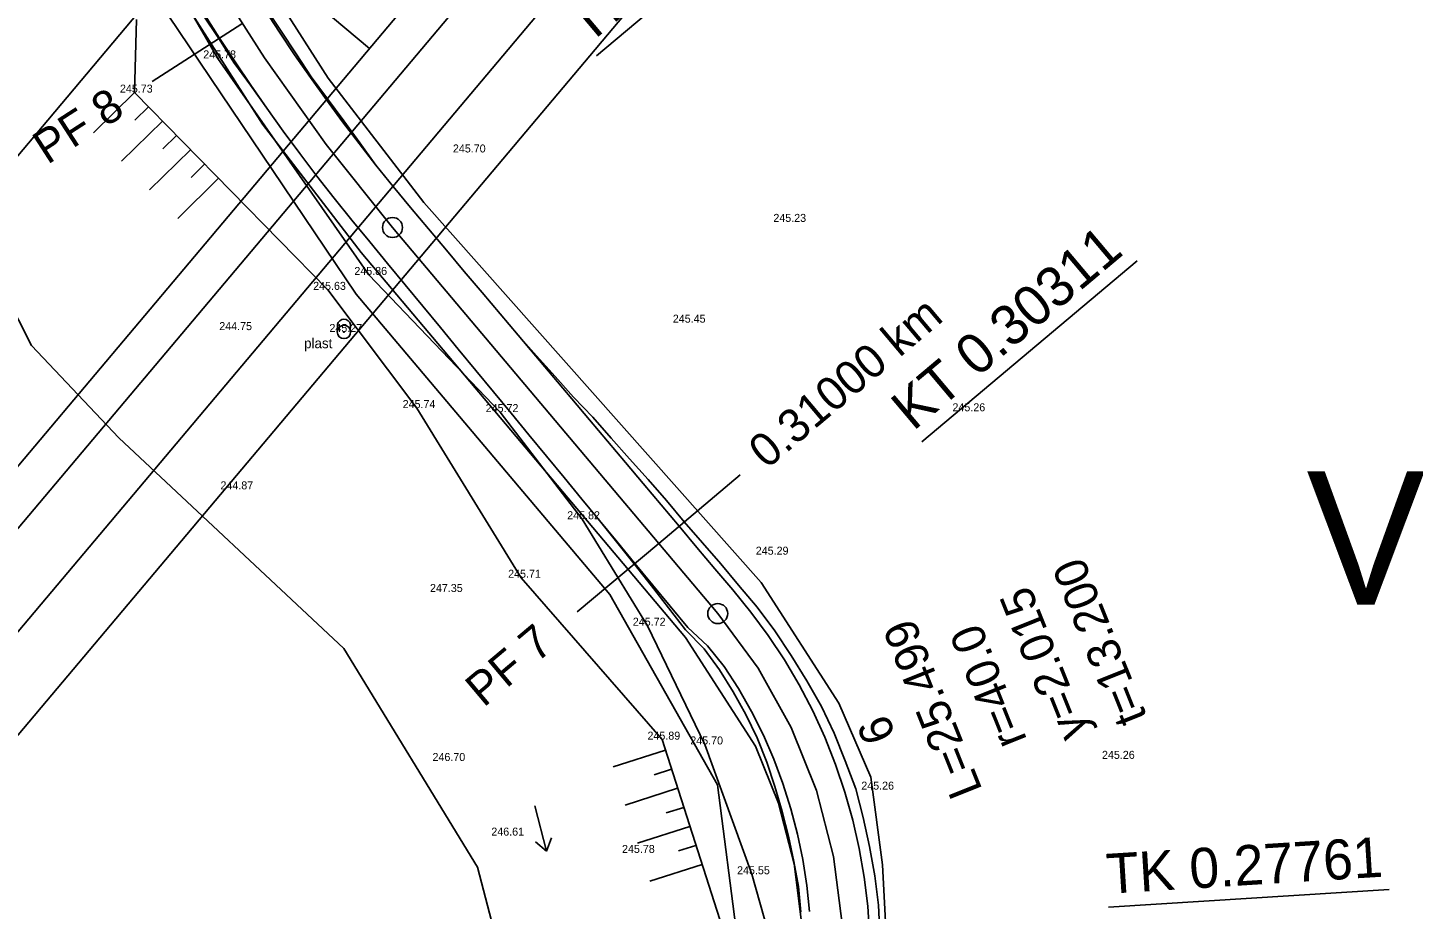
# Model space of a CAD drawing. Extents: x -555887 to -552101, y -1100251 to -1096546.
# Drawn here: x -554197.5 to -554093.6, y -1097070.3 to -1097004.2 of the extents above; entities that cross this region are included whole.
import ezdxf

# ---------------------------------------------------------------- set-up
doc = ezdxf.new("R2010")
doc.units = 0
for name, color, linetype in [('PARCELY_cesty', 7, 'Continuous'), ('PARCELY_VHO', 7, 'Continuous'), ('POLYGONY_POPIS_CESTY', 7, 'Continuous'), ('POLYGONY_SITUACE_PF', 7, 'Continuous'), ('POLYGONY_SITUACE_PF_POPISY', 7, 'Continuous'), ('POLYGONY_SITUACE_PO', 7, 'Continuous'), ('ram_VC2', 7, 'Continuous'), ('Výškopis', 7, 'Continuous'), ('ZSST', 7, 'Continuous'), ('zájem', 7, 'Continuous')]:
    doc.layers.add(name, color=color, linetype=linetype)

msp = doc.modelspace()

# ---------------------------------------------------------------- linework, layer by layer
for p, q in [((-554154.8, -1097006.31), (-554138.67, -1096992.72)), ((-554130.41, -1097035.28), (-554114.27, -1097021.69)), ((-554116.42, -1097070.19), (-554095.37, -1097068.87))]:
    msp.add_line(p, q)
at = {"layer": 'PARCELY_cesty'}
for points in [[(-554115.45, -1097149.45), (-554124.69, -1097127.01), (-554128.78, -1097114.84), (-554130.72, -1097105.51), (-554131.84, -1097095.95), (-554133.35, -1097067.01), (-554134.24, -1097060.44), (-554136.63, -1097054.87), (-554142.45, -1097045.83), (-554167.76, -1097017.31), (-554174.93, -1097007.99), (-554183.34, -1096994.77), (-554188.76, -1096984.33), (-554196.7, -1096967.2), (-554199.93, -1096958.08), (-554201.74, -1096948.89), (-554201.83, -1096939.45), (-554200.52, -1096930.03), (-554198.73, -1096923.96), (-554169.26, -1096840.86), (-554169, -1096840.13)], [(-554120.97, -1097151.79), (-554130.31, -1097129.11), (-554134.59, -1097116.42), (-554136.65, -1097106.48), (-554137.82, -1097096.49), (-554139.37, -1097071.71), (-554139.97, -1097066.94), (-554141.16, -1097062.38), (-554142.87, -1097058.1), (-554148.12, -1097049.95), (-554172.44, -1097021.07), (-554179.85, -1097011.43), (-554188.55, -1096997.77)]]:
    msp.add_lwpolyline(points, dxfattribs=at)
at = {"layer": 'PARCELY_VHO'}
for points in [[(-554130.46, -1097180.06), (-554159.17, -1097101.34), (-554159.64, -1097082.93), (-554163.72, -1097067.19), (-554173.74, -1097050.79), (-554190.63, -1097034.96), (-554197.16, -1097028.05), (-554217.46, -1096987.98), (-554225.33, -1096977.64), (-554234.21, -1096944.26), (-554236.99, -1096909.92), (-554235.22, -1096898.62), (-554228.6, -1096882.13), (-554225.73, -1096869.26), (-554224.9, -1096864.61), (-554220.11, -1096846.63), (-554200.4, -1096831.93), (-554179.17, -1096807.62), (-554142.08, -1096773.53), (-554110.69, -1096747.36), (-554089.18, -1096729.49)], [(-554093.55, -1096750.72), (-554107.61, -1096766.97), (-554183.58, -1096830.32), (-554190.17, -1096868.02), (-554206.15, -1096921.51), (-554210.92, -1096940.13), (-554208.99, -1096958.65), (-554201.43, -1096978.3), (-554189.25, -1096999.78), (-554172.82, -1097024.19), (-554153.8, -1097046.73), (-554145.73, -1097061.02), (-554142.77, -1097083.92), (-554141.5, -1097107.04), (-554133.09, -1097133.96)]]:
    msp.add_lwpolyline(points, dxfattribs=at)
at = {"layer": 'POLYGONY_SITUACE_PF'}
for p, q in [((-554188.12, -1097008.24), (-554181.39, -1097003.91)), ((-554150.14, -1097042.89), (-554144.02, -1097037.74)), ((-554156.26, -1097048.04), (-554150.14, -1097042.89))]:
    msp.add_line(p, q, dxfattribs=at)
at = {"layer": 'POLYGONY_SITUACE_PO'}
for p, q in [((-554179.71, -1097006.47), (-554183.99, -1096999.74)), ((-554178.58, -1097004.54), (-554179.71, -1097002.82)), ((-554178.58, -1097004.54), (-554179.71, -1097002.82)), ((-554178.45, -1097004.45), (-554179.59, -1097002.74)), ((-554183.12, -1097005.02), (-554184.29, -1097003.26)), ((-554183.08, -1097004.99), (-554184.2, -1097003.21)), ((-554181.99, -1097006.81), (-554183.12, -1097005.02)), ((-554181.91, -1097006.75), (-554183.08, -1097004.99)), ((-554177.44, -1097006.24), (-554178.58, -1097004.54)), ((-554177.44, -1097006.24), (-554178.58, -1097004.54)), ((-554177.33, -1097006.17), (-554178.45, -1097004.45)), ((-554180.74, -1097008.51), (-554181.99, -1097006.81)), ((-554180.73, -1097008.5), (-554181.91, -1097006.75)), ((-554175.07, -1097012.96), (-554179.71, -1097006.47)), ((-554176.26, -1097007.93), (-554177.44, -1097006.24)), ((-554176.26, -1097007.93), (-554177.44, -1097006.24)), ((-554176.2, -1097007.89), (-554177.33, -1097006.17)), ((-554175.06, -1097009.6), (-554176.26, -1097007.93)), ((-554175.06, -1097009.6), (-554176.26, -1097007.93)), ((-554174.97, -1097009.53), (-554176.2, -1097007.89)), ((-554179.53, -1097010.24), (-554180.74, -1097008.51)), ((-554179.53, -1097010.24), (-554180.73, -1097008.5)), ((-554178.3, -1097011.95), (-554179.53, -1097010.24)), ((-554179.53, -1097010.24), (-554179.53, -1097010.24)), ((-554178.3, -1097011.95), (-554179.53, -1097010.24)), ((-554173.85, -1097011.26), (-554175.06, -1097009.6)), ((-554173.85, -1097011.26), (-554175.06, -1097009.6)), ((-554173.76, -1097011.19), (-554174.97, -1097009.53)), ((-554172.6, -1097012.89), (-554173.85, -1097011.26)), ((-554172.6, -1097012.89), (-554173.85, -1097011.26)), ((-554172.54, -1097012.85), (-554173.76, -1097011.19)), ((-554177.05, -1097013.65), (-554178.3, -1097011.95)), ((-554177.05, -1097013.65), (-554178.3, -1097011.95)), ((-554170.1, -1097019.19), (-554175.07, -1097012.96)), ((-554171.34, -1097014.51), (-554172.6, -1097012.89)), ((-554171.34, -1097014.51), (-554172.6, -1097012.89)), ((-554171.34, -1097014.51), (-554172.54, -1097012.85)), ((-554175.77, -1097015.33), (-554177.05, -1097013.65)), ((-554175.77, -1097015.33), (-554177.05, -1097013.65)), ((-554174.47, -1097017), (-554175.77, -1097015.33)), ((-554174.47, -1097017), (-554175.77, -1097015.33)), ((-554170.05, -1097016.12), (-554171.34, -1097014.51)), ((-554170.05, -1097016.12), (-554171.34, -1097014.51)), ((-554170.05, -1097016.12), (-554171.34, -1097014.51)), ((-554171.34, -1097014.51), (-554171.34, -1097014.51)), ((-554168.74, -1097017.7), (-554170.05, -1097016.12)), ((-554168.74, -1097017.7), (-554170.05, -1097016.12)), ((-554168.74, -1097017.7), (-554170.05, -1097016.12)), ((-554173.15, -1097018.64), (-554174.47, -1097017)), ((-554173.15, -1097018.64), (-554174.47, -1097017)), ((-554167.4, -1097019.29), (-554168.74, -1097017.7)), ((-554167.4, -1097019.29), (-554168.74, -1097017.7)), ((-554167.4, -1097019.29), (-554168.74, -1097017.7)), ((-554171.8, -1097020.27), (-554173.15, -1097018.64)), ((-554171.8, -1097020.27), (-554173.15, -1097018.64)), ((-554145.71, -1097048.16), (-554170.1, -1097019.19)), ((-554166.06, -1097020.88), (-554167.4, -1097019.29)), ((-554166.06, -1097020.88), (-554167.4, -1097019.29)), ((-554166.06, -1097020.88), (-554167.4, -1097019.29)), ((-554170.47, -1097021.88), (-554171.8, -1097020.27)), ((-554170.47, -1097021.88), (-554171.8, -1097020.27)), ((-554164.72, -1097022.48), (-554166.06, -1097020.88)), ((-554164.72, -1097022.48), (-554166.06, -1097020.88)), ((-554164.72, -1097022.48), (-554166.06, -1097020.88)), ((-554169.15, -1097023.49), (-554170.47, -1097021.88)), ((-554169.15, -1097023.49), (-554170.47, -1097021.88)), ((-554163.37, -1097024.07), (-554164.72, -1097022.48)), ((-554163.37, -1097024.07), (-554164.72, -1097022.48)), ((-554163.37, -1097024.07), (-554164.72, -1097022.48)), ((-554167.82, -1097025.1), (-554169.15, -1097023.49)), ((-554167.82, -1097025.1), (-554169.15, -1097023.49)), ((-554162.03, -1097025.67), (-554163.37, -1097024.07)), ((-554162.03, -1097025.67), (-554163.37, -1097024.07)), ((-554162.03, -1097025.67), (-554163.37, -1097024.07)), ((-554166.5, -1097026.7), (-554167.82, -1097025.1)), ((-554166.5, -1097026.7), (-554167.82, -1097025.1)), ((-554160.69, -1097027.26), (-554162.03, -1097025.67)), ((-554160.69, -1097027.26), (-554162.03, -1097025.67)), ((-554160.69, -1097027.26), (-554162.03, -1097025.67)), ((-554165.17, -1097028.31), (-554166.5, -1097026.7)), ((-554165.17, -1097028.31), (-554166.5, -1097026.7)), ((-554159.35, -1097028.85), (-554160.69, -1097027.26)), ((-554159.35, -1097028.85), (-554160.69, -1097027.26)), ((-554159.3, -1097028.81), (-554160.69, -1097027.26)), ((-554160.69, -1097027.26), (-554160.69, -1097027.26)), ((-554163.85, -1097029.92), (-554165.17, -1097028.31)), ((-554163.85, -1097029.92), (-554165.17, -1097028.31)), ((-554158.01, -1097030.45), (-554159.35, -1097028.85)), ((-554158.01, -1097030.45), (-554159.35, -1097028.85)), ((-554157.91, -1097030.37), (-554159.3, -1097028.81)), ((-554162.52, -1097031.53), (-554163.85, -1097029.92)), ((-554162.52, -1097031.53), (-554163.85, -1097029.92)), ((-554156.66, -1097032.04), (-554158.01, -1097030.45)), ((-554156.66, -1097032.04), (-554158.01, -1097030.45)), ((-554156.53, -1097031.92), (-554157.91, -1097030.37)), ((-554161.2, -1097033.13), (-554162.52, -1097031.53)), ((-554161.2, -1097033.13), (-554162.52, -1097031.53)), ((-554155.32, -1097033.63), (-554156.66, -1097032.04)), ((-554155.32, -1097033.63), (-554156.66, -1097032.04)), ((-554155.07, -1097033.42), (-554156.53, -1097031.92)), ((-554159.87, -1097034.74), (-554161.2, -1097033.13)), ((-554159.87, -1097034.74), (-554161.2, -1097033.13)), ((-554153.98, -1097035.23), (-554155.32, -1097033.63)), ((-554153.98, -1097035.23), (-554155.32, -1097033.63)), ((-554153.71, -1097035), (-554155.07, -1097033.42)), ((-554158.55, -1097036.35), (-554159.87, -1097034.74)), ((-554158.55, -1097036.35), (-554159.87, -1097034.74)), ((-554152.64, -1097036.82), (-554153.98, -1097035.23)), ((-554152.64, -1097036.82), (-554153.98, -1097035.23)), ((-554152.33, -1097036.56), (-554153.71, -1097035)), ((-554157.22, -1097037.96), (-554158.55, -1097036.35)), ((-554157.22, -1097037.96), (-554158.55, -1097036.35)), ((-554151.3, -1097038.41), (-554152.64, -1097036.82)), ((-554151.3, -1097038.41), (-554152.64, -1097036.82)), ((-554150.93, -1097038.1), (-554152.33, -1097036.56)), ((-554155.9, -1097039.57), (-554157.22, -1097037.96)), ((-554155.9, -1097039.57), (-554157.22, -1097037.96)), ((-554149.56, -1097039.68), (-554150.93, -1097038.1)), ((-554149.96, -1097040.01), (-554151.3, -1097038.41)), ((-554149.96, -1097040.01), (-554151.3, -1097038.41)), ((-554154.57, -1097041.17), (-554155.9, -1097039.57)), ((-554154.57, -1097041.17), (-554155.9, -1097039.57)), ((-554148.61, -1097041.6), (-554149.96, -1097040.01)), ((-554148.61, -1097041.6), (-554149.96, -1097040.01)), ((-554148.22, -1097041.27), (-554149.56, -1097039.68)), ((-554153.27, -1097042.8), (-554154.57, -1097041.17)), ((-554154.57, -1097041.17), (-554154.57, -1097041.17)), ((-554153.25, -1097042.78), (-554154.57, -1097041.17)), ((-554146.85, -1097042.84), (-554148.22, -1097041.27)), ((-554147.27, -1097043.2), (-554148.61, -1097041.6)), ((-554147.27, -1097043.2), (-554148.61, -1097041.6)), ((-554151.97, -1097044.43), (-554153.27, -1097042.8)), ((-554151.92, -1097044.39), (-554153.25, -1097042.78)), ((-554145.93, -1097044.79), (-554147.27, -1097043.2)), ((-554145.93, -1097044.79), (-554147.27, -1097043.2)), ((-554145.49, -1097044.42), (-554146.85, -1097042.84)), ((-554150.68, -1097046.07), (-554151.97, -1097044.43)), ((-554150.6, -1097046), (-554151.92, -1097044.39)), ((-554144.15, -1097046.02), (-554145.49, -1097044.42)), ((-554144.59, -1097046.38), (-554145.93, -1097044.79)), ((-554144.59, -1097046.38), (-554145.93, -1097044.79)), ((-554149.41, -1097047.72), (-554150.68, -1097046.07)), ((-554149.27, -1097047.6), (-554150.6, -1097046)), ((-554143.22, -1097048.05), (-554144.59, -1097046.38)), ((-554143.22, -1097048.05), (-554144.59, -1097046.38)), ((-554142.75, -1097047.68), (-554144.15, -1097046.02)), ((-554147.95, -1097049.21), (-554149.27, -1097047.6)), ((-554141.43, -1097049.46), (-554142.75, -1097047.68)), ((-554148.14, -1097049.37), (-554149.41, -1097047.72)), ((-554142.68, -1097052.26), (-554145.71, -1097048.16)), ((-554141.92, -1097049.81), (-554143.22, -1097048.05)), ((-554141.92, -1097049.81), (-554143.22, -1097048.05)), ((-554146.74, -1097050.8), (-554148.14, -1097049.37)), ((-554146.47, -1097050.59), (-554147.95, -1097049.21)), ((-554140.21, -1097051.31), (-554141.43, -1097049.46)), ((-554145.57, -1097052.37), (-554146.74, -1097050.8)), ((-554145.22, -1097052.12), (-554146.47, -1097050.59)), ((-554140.71, -1097051.63), (-554141.92, -1097049.81)), ((-554140.71, -1097051.63), (-554141.92, -1097049.81)), ((-554139.6, -1097053.51), (-554140.71, -1097051.63)), ((-554139.6, -1097053.51), (-554140.71, -1097051.63)), ((-554139.04, -1097053.2), (-554140.21, -1097051.31)), ((-554144.56, -1097054.04), (-554145.57, -1097052.37)), ((-554144.15, -1097053.79), (-554145.22, -1097052.12)), ((-554140.2, -1097056.71), (-554142.68, -1097052.26)), ((-554143.18, -1097055.5), (-554144.15, -1097053.79)), ((-554138.58, -1097055.45), (-554139.6, -1097053.51)), ((-554138.58, -1097055.45), (-554139.6, -1097053.51)), ((-554137.94, -1097055.14), (-554139.04, -1097053.2)), ((-554143.61, -1097055.74), (-554144.56, -1097054.04)), ((-554142.75, -1097057.49), (-554143.61, -1097055.74)), ((-554142.29, -1097057.27), (-554143.18, -1097055.5)), ((-554137.68, -1097057.44), (-554138.58, -1097055.45)), ((-554137.68, -1097057.44), (-554138.58, -1097055.45)), ((-554136.97, -1097057.14), (-554137.94, -1097055.14)), ((-554138.3, -1097061.44), (-554140.2, -1097056.71)), ((-554142.04, -1097059.3), (-554142.75, -1097057.49)), ((-554141.51, -1097059.08), (-554142.29, -1097057.27)), ((-554136.87, -1097059.48), (-554137.68, -1097057.44)), ((-554136.87, -1097059.48), (-554137.68, -1097057.44)), ((-554136.15, -1097059.21), (-554136.97, -1097057.14)), ((-554140.82, -1097060.92), (-554141.51, -1097059.08)), ((-554141.42, -1097061.14), (-554142.04, -1097059.3)), ((-554136.17, -1097061.55), (-554136.87, -1097059.48)), ((-554136.17, -1097061.55), (-554136.87, -1097059.48)), ((-554135.36, -1097061.3), (-554136.15, -1097059.21)), ((-554140.88, -1097063), (-554141.42, -1097061.14)), ((-554140.22, -1097062.8), (-554140.82, -1097060.92)), ((-554137.02, -1097066.38), (-554138.3, -1097061.44)), ((-554135.58, -1097063.65), (-554136.17, -1097061.55)), ((-554135.58, -1097063.65), (-554136.17, -1097061.55)), ((-554134.8, -1097063.46), (-554135.36, -1097061.3)), ((-554140.41, -1097064.87), (-554140.88, -1097063)), ((-554139.72, -1097064.7), (-554140.22, -1097062.8)), ((-554135.1, -1097065.79), (-554135.58, -1097063.65)), ((-554135.1, -1097065.79), (-554135.58, -1097063.65)), ((-554134.33, -1097065.63), (-554134.8, -1097063.46)), ((-554140, -1097066.75), (-554140.41, -1097064.87)), ((-554139.33, -1097066.62), (-554139.72, -1097064.7)), ((-554136.38, -1097071.43), (-554137.02, -1097066.38)), ((-554134.74, -1097067.94), (-554135.1, -1097065.79)), ((-554134.74, -1097067.94), (-554135.1, -1097065.79)), ((-554133.94, -1097067.83), (-554134.33, -1097065.63)), ((-554139.66, -1097068.65), (-554140, -1097066.75)), ((-554139.04, -1097068.56), (-554139.33, -1097066.62)), ((-554134.47, -1097070.11), (-554134.74, -1097067.94)), ((-554134.47, -1097070.11), (-554134.74, -1097067.94)), ((-554133.67, -1097070.04), (-554133.94, -1097067.83)), ((-554139.47, -1097070.57), (-554139.66, -1097068.65)), ((-554138.84, -1097070.51), (-554139.04, -1097068.56)), ((-554134.33, -1097072.25), (-554134.47, -1097070.11)), ((-554134.33, -1097072.25), (-554134.47, -1097070.11)), ((-554133.56, -1097072.2), (-554133.67, -1097070.04))]:
    msp.add_line(p, q, dxfattribs=at)
for centre in [(-554170.1, -1097019.19), (-554145.71, -1097048.16)]:
    msp.add_circle(centre, 0.75, dxfattribs=at)
at = {"layer": 'ram_VC2'}
for p, q in [((-554260.57, -1097087.91), (-554144.67, -1096950.19)), ((-554217.74, -1096967.12), (-554171.83, -1097005.76))]:
    msp.add_line(p, q, dxfattribs=at)
for points in [[(-554114.88, -1096958.27), (-554342.13, -1096767.04), (-555018.18, -1097570.44), (-554790.93, -1097761.67)], [(-554121.93, -1096958.88), (-554341.52, -1096774.09), (-555011.14, -1097569.84), (-554791.54, -1097754.63)], [(-554299.23, -1097059.3), (-554179.47, -1096916.99), (-554128.97, -1096959.48), (-554248.73, -1097101.8)], [(-554295, -1097058.94), (-554179.11, -1096921.22), (-554133.2, -1096959.85), (-554249.09, -1097097.57)]]:
    msp.add_lwpolyline(points, close=True, dxfattribs=at)
for points in [[(-554114.88, -1096958.27), (-554342.13, -1096767.04), (-555018.18, -1097570.44), (-554790.93, -1097761.67), (-554114.88, -1096958.27)], [(-554791.54, -1097754.63), (-555011.14, -1097569.84), (-554341.52, -1096774.09), (-554121.93, -1096958.88), (-554791.54, -1097754.63)]]:
    msp.add_lwpolyline(points, dxfattribs=at)
at = {"layer": 'ZSST'}
for p, q in [((-554189.44, -1097009.07), (-554192.51, -1097012.08)), ((-554188.39, -1097010.14), (-554189.41, -1097011.14)), ((-554187.34, -1097011.21), (-554190.41, -1097014.22)), ((-554186.29, -1097012.28), (-554187.31, -1097013.29)), ((-554185.24, -1097013.36), (-554188.31, -1097016.37)), ((-554184.19, -1097014.43), (-554185.21, -1097015.43)), ((-554183.14, -1097015.5), (-554186.21, -1097018.51)), ((-554149.64, -1097058.41), (-554153.56, -1097059.67)), ((-554149.18, -1097059.84), (-554150.49, -1097060.26)), ((-554148.72, -1097061.27), (-554152.65, -1097062.53)), ((-554159.43, -1097062.59), (-554158.56, -1097065.98)), ((-554148.26, -1097062.7), (-554149.57, -1097063.12)), ((-554147.8, -1097064.13), (-554151.73, -1097065.39)), ((-554158.56, -1097065.98), (-554159.38, -1097065.29)), ((-554158.18, -1097064.98), (-554158.56, -1097065.98)), ((-554147.35, -1097065.56), (-554148.65, -1097065.97)), ((-554146.89, -1097066.98), (-554150.81, -1097068.24))]:
    msp.add_line(p, q, dxfattribs=at)
for points in [[(-554127.72, -1097139.75), (-554132.59, -1097127.58), (-554135.61, -1097117.54), (-554137.88, -1097105.57), (-554138.99, -1097087.27), (-554140.38, -1097077.55), (-554143.15, -1097067.72), (-554146.69, -1097057.98), (-554150.99, -1097049.07), (-554155.89, -1097041.08), (-554162.02, -1097033.04), (-554171.87, -1097022.75), (-554183.21, -1097006.5), (-554191.67, -1096991.83)], [(-554134.49, -1097136.49), (-554138.97, -1097119.53), (-554145.35, -1097101.44), (-554143.32, -1097094.49), (-554144.36, -1097083.89), (-554145.36, -1097071.75), (-554149.89, -1097057.62), (-554160.46, -1097045.47), (-554168.27, -1097032.74), (-554174.94, -1097023.87), (-554189.44, -1097009.07), (-554189.29, -1097003.58)]]:
    msp.add_lwpolyline(points, dxfattribs=at)
for radius in [0.5, 0.0327]:
    msp.add_circle((-554173.74, -1097027.03), radius, dxfattribs=at)
msp.add_arc((-554173.74, -1097026.57), 0.5, 331.7891, 208.7844, dxfattribs=at)
at = {"layer": 'zájem'}
for points in [[(-554130.46, -1097180.06), (-554159.17, -1097101.34), (-554159.64, -1097082.93), (-554163.72, -1097067.19), (-554173.74, -1097050.79), (-554190.63, -1097034.96), (-554197.16, -1097028.05), (-554217.46, -1096987.98)], [(-554217.46, -1096987.98), (-554197.16, -1097028.05), (-554190.63, -1097034.96), (-554173.74, -1097050.79), (-554163.72, -1097067.19), (-554159.64, -1097082.93), (-554159.17, -1097101.34), (-554130.46, -1097180.06)]]:
    msp.add_lwpolyline(points, dxfattribs=at)

# ---------------------------------------------------------------- texts
for s, height, rotation, p in [('TK 0.34098', 3, 40.0977, (-554155.45, -1097005.54)), ('KT 0.30311', 3, 40.0977, (-554131.05, -1097034.51)), ('t=13.200', 2.5, 111.8351, (-554113.48, -1097055.94)), ('y=2.015', 2.5, 111.8351, (-554117.88, -1097057.06)), ('L=25.499', 2.5, 111.8351, (-554125.84, -1097061.39)), ('r=40.0', 2.5, 111.8351, (-554122.5, -1097057.63)), ('6', 2.5, 111.8351, (-554132.32, -1097057.32)), ('TK 0.27761', 3, 3.5724, (-554116.48, -1097069.19))]:
    msp.add_text(s, height=height, rotation=rotation).set_placement(p)
at = {"layer": 'POLYGONY_POPIS_CESTY'}
msp.add_text('VC6', height=10, dxfattribs=at).set_placement((-554101.57, -1097047.48))
at = {"layer": 'POLYGONY_SITUACE_PF_POPISY'}
for s, rotation, p in [('PF 8', 32.8344, (-554195.98, -1097014.51)), ('0.31000 km', 40.0977, (-554142.04, -1097037.37)), ('PF 7', 40.0977, (-554163.27, -1097055.25))]:
    msp.add_text(s, height=2.5, rotation=rotation, dxfattribs=at).set_placement(p)
at = {"layer": 'ram_VC2'}
msp.add_text('Komplexní pozemkové úpravy v  k.ú. Nová Dědina u Uničova', height=3, rotation=49.9197, dxfattribs=at).set_placement((-554261.57, -1097064.25))
at = {"layer": 'Výškopis'}
for s, p in [('245.78', (-554184.29, -1097006.5)), ('245.73', (-554190.54, -1097009.07)), ('245.70', (-554165.57, -1097013.56)), ('245.23', (-554141.54, -1097018.77)), ('245.86', (-554172.96, -1097022.75)), ('245.63', (-554176.05, -1097023.87)), ('245.45', (-554149.08, -1097026.33)), ('244.75', (-554183.09, -1097026.89)), ('245.27', (-554174.83, -1097027.03)), ('245.74', (-554169.34, -1097032.74)), ('245.72', (-554163.11, -1097033.04)), ('245.26', (-554128.11, -1097032.98)), ('244.87', (-554183, -1097038.84)), ('245.82', (-554157, -1097041.08)), ('245.29', (-554142.86, -1097043.74)), ('245.71', (-554161.43, -1097045.47)), ('247.35', (-554167.29, -1097046.54)), ('245.72', (-554152.08, -1097049.07)), ('245.89', (-554150.98, -1097057.62)), ('245.70', (-554147.77, -1097057.98)), ('246.70', (-554167.1, -1097059.22)), ('245.26', (-554116.9, -1097059.06)), ('245.26', (-554134.95, -1097061.37)), ('246.61', (-554162.69, -1097064.82)), ('245.78', (-554152.89, -1097066.12)), ('245.55', (-554144.26, -1097067.72))]:
    msp.add_text(s, height=0.6, dxfattribs=at).set_placement(p)
at = {"layer": 'ZSST'}
msp.add_text('plast', height=0.75, dxfattribs=at).set_placement((-554176.73, -1097028.25))

doc.saveas('drawing.dxf')
